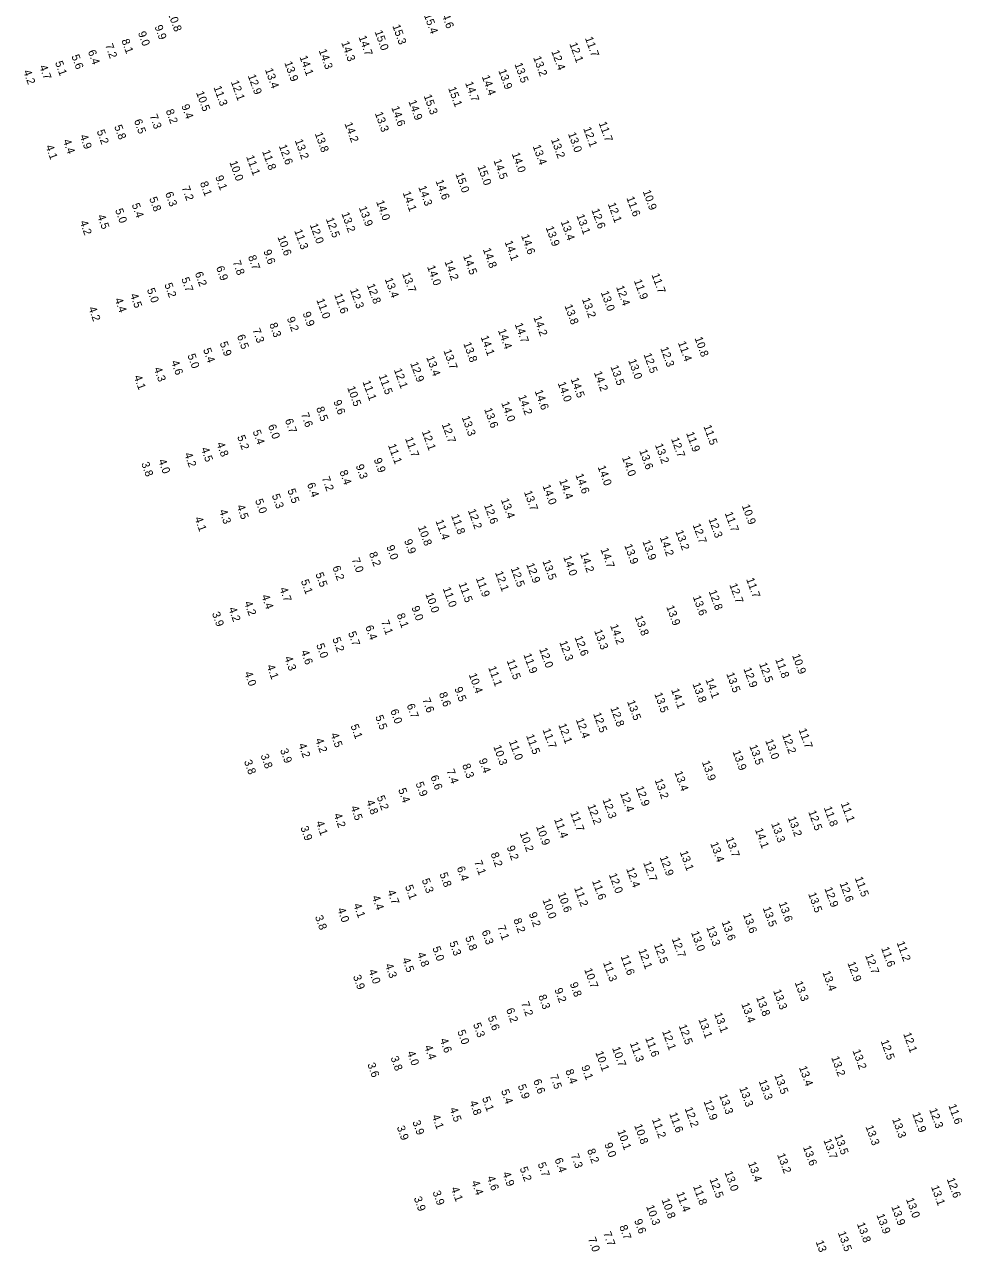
# Model space of a CAD drawing. Extents: x 815385 to 820851, y 582449 to 604245.
# Drawn here: x 819938 to 820525, y 591711 to 592474 of the extents above; entities that cross this region are included whole.
import ezdxf

# ---------------------------------------------------------------- set-up
doc = ezdxf.new("R2010")
doc.units = 0
doc.layers.add('V-TOPO-SOUN-112008', color=7, linetype='Continuous')

msp = doc.modelspace()

# ---------------------------------------------------------------- texts
at = {"layer": 'V-TOPO-SOUN-112008'}
for s, p in [('10.8 ', (820027.94, 592480.84)), ('15.4 ', (820187.99, 592479.46)), ('14.6 ', (820197.95, 592482.8)), ('9.0', (820009.34, 592468.38)), ('9.9', (820019.71, 592472.29)), ('15.0 ', (820157.19, 592469.11)), ('15.3 ', (820168.27, 592472.72)), ('7.2', (819988.81, 592460.69)), ('8.1', (819998.99, 592463.65)), ('14.3 ', (820136.35, 592462.24)), ('14.7 ', (820147.16, 592465.75)), ('12.1 ', (820278.88, 592461.51)), ('11.7 ', (820288.62, 592465.08)), ('5.6', (819967.77, 592453.87)), ('6.4', (819978.04, 592456.75)), ('14.1 ', (820110.29, 592453.26)), ('14.3 ', (820122.26, 592457.36)), ('12.4 ', (820267.59, 592456.73)), ('4.7', (819947.71, 592447.38)), ('5.1', (819957.5, 592449.83)), ('13.4 ', (820088.68, 592445.36)), ('13.9 ', (820100.78, 592449.69)), ('13.5 ', (820244.56, 592448.81)), ('13.2 ', (820256.27, 592452.93)), ('4.2', (819937.67, 592444.31)), ('12.1 ', (820067.37, 592437.78)), ('12.9 ', (820077.98, 592441.55)), ('14.4 ', (820224.16, 592441.02)), ('13.9 ', (820234.48, 592444.78)), ('10.5 ', (820045.64, 592431.04)), ('11.3 ', (820056.54, 592434.36)), ('15.1 ', (820203.13, 592433.8)), ('14.7 ', (820213.75, 592437.04)), ('9.4', (820036.43, 592422.8)), ('14.9 ', (820178.33, 592425.5)), ('15.3 ', (820187.85, 592429)), ('7.3', (820016.58, 592416.55)), ('8.2', (820026.71, 592419.74)), ('13.3 ', (820157.34, 592418.12)), ('14.6 ', (820167.62, 592421.69)), ('5.2', (819983.59, 592406.93)), ('5.8', (819994.49, 592409.92)), ('6.5', (820006.86, 592413.5)), ('14.2 ', (820138.39, 592411.62)), ('12.1 ', (820287.52, 592408.65)), ('11.7 ', (820297.2, 592411.99)), ('4.4', (819962.49, 592400.99)), ('4.9', (819972.99, 592403.95)), ('13.2 ', (820107.33, 592401.07)), ('13.8 ', (820119.81, 592405.42)), ('13.2 ', (820267.38, 592401.68)), ('13.0 ', (820278.01, 592405.38)), ('4.1', (819951.62, 592397.45)), ('11.8 ', (820086.9, 592394.32)), ('12.6 ', (820097.34, 592397.7)), ('14.0 ', (820242.89, 592392.77)), ('13.4 ', (820255.97, 592397.55)), ('10.0 ', (820066.45, 592387.54)), ('11.1 ', (820076.95, 592390.99)), ('15.0 ', (820221.42, 592384.83)), ('14.5 ', (820231.45, 592388.59)), ('9.1', (820057.63, 592378.31)), ('15.0 ', (820207.67, 592380.19)), ('7.2', (820036.7, 592371.72)), ('8.1', (820048.07, 592374.61)), ('14.3 ', (820184.5, 592371.96)), ('14.6 ', (820195.28, 592375.77)), ('10.9 ', (820324.72, 592369.32)), ('5.8', (820016.36, 592364.94)), ('6.3', (820026.3, 592368.09)), ('14.0 ', (820158.13, 592362.85)), ('14.1 ', (820174.71, 592368.45)), ('11.6 ', (820314.48, 592365.28)), ('5.0', (819995.04, 592357.68)), ('5.4', (820005.43, 592361.02)), ('13.2 ', (820136.44, 592355.45)), ('13.9 ', (820147.35, 592359.14)), ('13.1 ', (820283.28, 592354.19)), ('12.6 ', (820292.65, 592357.69)), ('12.1 ', (820302.9, 592361.44)), ('4.2', (819972.96, 592350.23)), ('4.5', (819983.93, 592353.94)), ('12.0 ', (820116.69, 592348.38)), ('12.5 ', (820126.75, 592352.06)), ('13.9 ', (820264.07, 592346.71)), ('13.4 ', (820273.46, 592350.36)), ('10.6 ', (820096.51, 592340.81)), ('11.3 ', (820106.98, 592344.76)), ('14.6 ', (820248.73, 592341.6)), ('9.6', (820087.7, 592331.98)), ('14.8 ', (820224.81, 592333.09)), ('14.1 ', (820238.44, 592337.67)), ('7.8', (820068.49, 592325.21)), ('8.7', (820078.1, 592328.51)), ('14.2 ', (820200.88, 592325.4)), ('14.5 ', (820212.48, 592328.93)), ('6.2', (820044.87, 592318.17)), ('6.9', (820058.13, 592321.75)), ('13.7 ', (820174.38, 592317.84)), ('14.0 ', (820189.99, 592322.19)), ('11.7 ', (820330.22, 592317.25)), ('5.0', (820014.91, 592307.94)), ('5.2', (820025.82, 592311.18)), ('5.7', (820036.39, 592314.68)), ('12.8 ', (820152.37, 592310.76)), ('13.4 ', (820163.53, 592314.47)), ('12.4 ', (820308.05, 592309.58)), ('11.9 ', (820319.2, 592313.5)), ('4.4', (819994.75, 592301.84)), ('4.5', (820004.41, 592304.65)), ('11.0 ', (820120.81, 592301.46)), ('11.6 ', (820131.96, 592304.67)), ('12.3 ', (820141.8, 592307.8)), ('13.2 ', (820286.72, 592301.93)), ('13.0 ', (820298.51, 592306.21)), ('4.2', (819978.39, 592296.39)), ('9.9', (820112.21, 592293.14)), ('13.8 ', (820275.82, 592297.82)), ('8.3', (820091.36, 592286.34)), ('9.2', (820102.35, 592289.98)), ('14.7 ', (820244.72, 592286.29)), ('14.2 ', (820256.4, 592290.62)), ('6.5', (820071.17, 592278.95)), ('7.3', (820080.81, 592282.82)), ('14.1 ', (820223.44, 592278.34)), ('14.4 ', (820234.26, 592282.47)), ('10.8 ', (820357.07, 592277.62)), ('5.4', (820050.02, 592270.47)), ('5.9', (820060.4, 592274.54)), ('13.8 ', (820212.59, 592274.25)), ('12.3 ', (820335.68, 592271.33)), ('11.4 ', (820346.69, 592274.79)), ('4.6', (820030.01, 592262.83)), ('5.0', (820040.25, 592266.89)), ('13.4 ', (820189.48, 592265.59)), ('13.7 ', (820200.19, 592269.76)), ('13.0 ', (820315.62, 592263.66)), ('12.5 ', (820325.21, 592267.41)), ('4.3', (820019.27, 592258.6)), ('12.1 ', (820169.24, 592257.88)), ('12.9 ', (820179.41, 592261.87)), ('14.2 ', (820294.21, 592256.06)), ('13.5 ', (820304.53, 592259.8)), ('4.1', (820006.77, 592253.58)), ('11.1 ', (820149.62, 592250.31)), ('11.5 ', (820159.7, 592254.11)), ('14.0 ', (820271.59, 592249.51)), ('14.5 ', (820279.67, 592252.05)), ('10.5 ', (820140.05, 592246.7)), ('14.2 ', (820246.9, 592241.25)), ('14.6 ', (820257.21, 592244.49)), ('8.5', (820120.66, 592233.87)), ('9.6', (820131.41, 592238.07)), ('13.6 ', (820225.63, 592233.16)), ('14.0 ', (820236.29, 592237.1)), ('6.7', (820101.13, 592226.39)), ('7.6', (820111.12, 592230.18)), ('13.3 ', (820211.62, 592228.14)), ('5.4', (820080.98, 592219.34)), ('6.0', (820090.57, 592222.82)), ('12.1 ', (820186.71, 592219.21)), ('12.7 ', (820199.14, 592223.78)), ('11.9 ', (820351.81, 592218.23)), ('11.5 ', (820362.64, 592222.54)), ('4.8', (820058.41, 592211.71)), ('5.2', (820071.31, 592216.04)), ('11.1 ', (820165.56, 592210.71)), ('11.7 ', (820176.21, 592214.89)), ('13.2 ', (820332.36, 592210.9)), ('12.7 ', (820342.42, 592214.68)), ('4.2', (820038.3, 592205.21)), ('4.5', (820048.69, 592208.52)), ('9.9', (820156.62, 592201.78)), ('14.0 ', (820311.72, 592203)), ('13.6 ', (820322.51, 592207.24)), ('3.8', (820011.39, 592199.33)), ('4.0', (820022.02, 592201.16)), ('8.4', (820135.24, 592194.2)), ('9.3', (820145.39, 592197.86)), ('14.0 ', (820296.54, 592197.16)), ('6.4', (820114.95, 592186.42)), ('7.2', (820124.19, 592190.27)), ('14.4 ', (820272.48, 592188.66)), ('14.6 ', (820282.65, 592192.11)), ('5.3', (820092.96, 592179.35)), ('5.5', (820102.7, 592182.61)), ('13.7 ', (820250.51, 592181.46)), ('14.0 ', (820262.12, 592185.25)), ('4.5', (820070.99, 592172.64)), ('5.0', (820082.49, 592176.25)), ('12.6 ', (820225.54, 592173.21)), ('13.4 ', (820236.09, 592176.66)), ('10.9 ', (820386.63, 592172.87)), ('4.1', (820044.71, 592165.07)), ('4.3', (820060.03, 592169.7)), ('11.4 ', (820195.26, 592163.35)), ('11.8 ', (820204.99, 592166.7)), ('12.2 ', (820215.47, 592169.98)), ('12.3 ', (820365.8, 592164.52)), ('11.7 ', (820375.96, 592168.22)), ('10.8 ', (820184.22, 592159.6)), ('13.2 ', (820345.1, 592156.83)), ('12.7 ', (820355.89, 592160.92)), ('9.9', (820175.63, 592151.06)), ('13.9 ', (820313.18, 592148.08)), ('13.9 ', (820324.48, 592150.56)), ('14.2 ', (820335.35, 592153.06)), ('8.2', (820153.67, 592143.17)), ('9.0', (820164.55, 592147.34)), ('14.0 ', (820275.06, 592140.77)), ('14.2 ', (820285.56, 592142.89)), ('14.7 ', (820298.34, 592145.63)), ('6.2', (820130.81, 592134.44)), ('7.0', (820142.84, 592139.42)), ('12.5 ', (820242.24, 592133.83)), ('12.9 ', (820251.94, 592136.27)), ('13.5 ', (820262.05, 592138.23)), ('5.1', (820111.11, 592125.89)), ('5.5', (820120.22, 592130.3)), ('11.9 ', (820220.44, 592127.58)), ('12.1 ', (820232.42, 592131.14)), ('11.7 ', (820389.34, 592127.01)), ('4.7', (820097.77, 592121.07)), ('10.0 ', (820188.88, 592117.71)), ('11.0 ', (820199.76, 592121.19)), ('11.5 ', (820209.65, 592124.18)), ('12.8 ', (820365.91, 592119.36)), ('12.7 ', (820378.82, 592123.56)), ('4.2', (820075.69, 592112.39)), ('4.4', (820086.49, 592116.52)), ('13.6 ', (820356, 592115.97)), ('3.9', (820055.55, 592105.66)), ('4.2', (820065.9, 592108.63)), ('8.1', (820171.01, 592104.79)), ('9.0', (820180.21, 592109.33)), ('13.8 ', (820319.75, 592103.39)), ('13.9 ', (820339.4, 592109.78)), ('6.4', (820151.34, 592097.27)), ('7.1', (820161.19, 592100.51)), ('13.3 ', (820294.36, 592094.73)), ('14.2 ', (820304.34, 592097.99)), ('5.2', (820130.8, 592089.76)), ('5.7', (820140.59, 592093.45)), ('12.3 ', (820272.56, 592087.64)), ('12.6 ', (820282.11, 592090.73)), ('4.6', (820111.09, 592081.84)), ('5.0', (820120.7, 592085.92)), ('11.9 ', (820250.17, 592079.8)), ('12.0 ', (820260.03, 592083.27)), ('10.9 ', (820418.01, 592079.41)), ('4.1', (820089.73, 592072.75)), ('4.3', (820100.79, 592078.01)), ('11.1 ', (820228.15, 592071.79)), ('11.5 ', (820239.74, 592076.02)), ('12.5 ', (820397.38, 592074.09)), ('11.8 ', (820407.48, 592076.9)), ('4.0', (820075.82, 592068.41)), ('10.4 ', (820216.01, 592067.39)), ('14.1 ', (820363.89, 592064.24)), ('13.5 ', (820376.93, 592067.88)), ('12.9 ', (820387.63, 592070.98)), ('9.5', (820207.03, 592058.75)), ('14.1 ', (820342.45, 592057.85)), ('13.8 ', (820355.8, 592061.54)), ('7.6', (820186.94, 592051.84)), ('8.6', (820197.37, 592055.52)), ('13.5 ', (820314.91, 592050.53)), ('13.5 ', (820331.96, 592055.3)), ('5.5', (820157.6, 592041.15)), ('6.0', (820167.01, 592044.88)), ('6.7', (820177.21, 592048.29)), ('12.5 ', (820293.73, 592042.87)), ('12.8 ', (820304.48, 592046.53)), ('5.1', (820142.14, 592035.45)), ('12.1 ', (820271.98, 592035.98)), ('12.4 ', (820282.9, 592039.29)), ('4.2', (820120.1, 592026.74)), ('4.5', (820129.63, 592030.09)), ('11.5 ', (820251.83, 592029.26)), ('11.7 ', (820262.09, 592032.91)), ('13.0 ', (820401.22, 592026.15)), ('12.2 ', (820411.77, 592029.63)), ('11.7 ', (820422.09, 592032.92)), ('3.9', (820098.13, 592020.29)), ('4.2', (820109.53, 592023.6)), ('10.3 ', (820231.33, 592022.44)), ('11.0 ', (820241.08, 592025.63)), ('13.9 ', (820380.82, 592019.24)), ('13.5 ', (820391.33, 592022.72)), ('3.8', (820075.59, 592013.21)), ('3.8', (820085.93, 592016.91)), ('8.3', (820211.89, 592010.84)), ('9.4', (820222.27, 592014.1)), ('13.9 ', (820361.65, 592012.76)), ('6.6', (820192.05, 592003.6)), ('7.4', (820202.11, 592007.43)), ('13.4 ', (820344.53, 592006.28)), ('5.4', (820171.91, 591995.53)), ('5.9', (820182.79, 591999.46)), ('12.9 ', (820320.3, 591996.88)), ('13.2 ', (820332.15, 592001.48)), ('5.2', (820158.52, 591990.93)), ('12.3 ', (820299.56, 591989.15)), ('12.4 ', (820310.52, 591993.26)), ('4.5', (820142.16, 591984.55)), ('4.8', (820151.93, 591988.18)), ('11.7 ', (820279.4, 591981.09)), ('12.2 ', (820290.15, 591985.47)), ('12.5 ', (820428.1, 591981.69)), ('11.8 ', (820437.84, 591984.21)), ('11.1 ', (820448.46, 591986.83)), ('4.1', (820120.47, 591975.08)), ('4.2', (820131.62, 591979.87)), ('11.4 ', (820269.32, 591976.92)), ('13.3 ', (820404.94, 591974.2)), ('13.2 ', (820415.4, 591977.86)), ('3.9', (820110.81, 591971.85)), ('10.2 ', (820247.83, 591968.39)), ('10.9 ', (820258.04, 591972.46)), ('14.1 ', (820394.83, 591970.57)), ('9.2', (820239.7, 591959.63)), ('13.4 ', (820366.87, 591961.91)), ('13.7 ', (820376.52, 591964.92)), ('7.1', (820219.35, 591950.41)), ('8.2', (820229.66, 591955.42)), ('12.7 ', (820324.98, 591949.82)), ('12.9 ', (820335.34, 591953.28)), ('13.1 ', (820347.88, 591956.49)), ('5.8', (820197.75, 591942.83)), ('6.4', (820208.51, 591946.68)), ('12.0 ', (820303.56, 591942.42)), ('12.4 ', (820314.36, 591946.03)), ('5.1', (820176.18, 591935.06)), ('5.3', (820186.62, 591939.09)), ('11.6 ', (820293.05, 591938.36)), ('12.6 ', (820447.68, 591936.98)), ('11.5 ', (820457.19, 591940.28)), ('4.4', (820155.48, 591928.5)), ('4.7', (820165.09, 591931.95)), ('10.6 ', (820271.57, 591930.49)), ('11.2 ', (820281.83, 591934.11)), ('13.5 ', (820428.07, 591930.42)), ('12.9 ', (820438.21, 591933.72)), ('4.0', (820133.86, 591920.82)), ('4.1', (820143.92, 591923.59)), ('10.0 ', (820262.05, 591926.59)), ('13.5 ', (820399.68, 591921.53)), ('13.6 ', (820409.61, 591924.6)), ('3.8', (820119.92, 591916.09)), ('8.2', (820243.9, 591914.24)), ('9.2', (820253.48, 591918)), ('13.6 ', (820374, 591912.82)), ('13.6 ', (820387.34, 591917.48)), ('6.3', (820224.04, 591906.88)), ('7.1', (820233.89, 591909.79)), ('13.0 ', (820354.87, 591906.24)), ('13.3 ', (820364.47, 591909.47)), ('5.0', (820193.26, 591896.62)), ('5.3', (820203.83, 591899.93)), ('5.8', (820213.77, 591903.17)), ('12.5 ', (820331.71, 591898.54)), ('12.7 ', (820342.85, 591902.26)), ('11.6 ', (820473.65, 591896.45)), ('11.2 ', (820483.34, 591899.92)), ('4.5', (820174.37, 591889.63)), ('4.8', (820183.79, 591893.02)), ('11.6 ', (820310.9, 591891.29)), ('12.1 ', (820321.94, 591895.19)), ('12.7 ', (820463.64, 591891.98)), ('4.0', (820153.38, 591882.37)), ('4.3', (820163.68, 591885.97)), ('10.7 ', (820288.14, 591883.1)), ('11.3 ', (820299.89, 591887.34)), ('13.4 ', (820436.95, 591881.39)), ('12.9 ', (820452.61, 591887.18)), ('3.9', (820143.66, 591878.83)), ('9.8', (820279.1, 591874.25)), ('13.3 ', (820419.65, 591874.97)), ('8.3', (820259.42, 591866.51)), ('9.2', (820269.55, 591870.62)), ('13.3 ', (820406.2, 591869.81)), ('7.2', (820248.71, 591862.17)), ('13.4 ', (820386.29, 591861.57)), ('13.8 ', (820395.55, 591865.66)), ('5.6', (820227.84, 591853.25)), ('6.2', (820239.32, 591858.13)), ('13.1 ', (820359.48, 591851.91)), ('13.1 ', (820369.34, 591855.35)), ('5.0', (820208.84, 591844.5)), ('5.3', (820218.67, 591848.92)), ('12.1 ', (820336.82, 591844.45)), ('12.5 ', (820347.18, 591847.93)), ('4.6', (820197.97, 591839.28)), ('11.3 ', (820316.67, 591837.07)), ('11.6 ', (820326.25, 591840.24)), ('12.5 ', (820473.34, 591838.36)), ('12.1 ', (820487.45, 591842.91)), ('3.8', (820167.14, 591828.04)), ('4.0', (820177.46, 591831.34)), ('4.4', (820188.22, 591835.01)), ('10.1 ', (820295.09, 591831.27)), ('10.7 ', (820305.56, 591834.04)), ('13.2 ', (820442.48, 591828.1)), ('13.2 ', (820455.78, 591832.38)), ('3.6', (820152.64, 591823.96)), ('8.4', (820276.37, 591819.9)), ('9.1', (820286.29, 591822.39)), ('13.4 ', (820422.32, 591821.95)), ('6.6', (820256.28, 591813.67)), ('7.5', (820266.71, 591816.64)), ('13.3 ', (820397.15, 591813.3)), ('13.5 ', (820406.92, 591816.97)), ('5.4', (820236.16, 591807.33)), ('5.9', (820246.64, 591810.48)), ('13.3 ', (820385.01, 591809.02)), ('4.8', (820216.45, 591800.3)), ('5.1', (820224.31, 591802.76)), ('12.9 ', (820362.69, 591800.68)), ('13.3 ', (820372.48, 591804.37)), ('11.6 ', (820515.64, 591798.16)), ('4.1', (820192.96, 591791.57)), ('4.5', (820203.98, 591796.11)), ('11.6 ', (820341.27, 591792.93)), ('12.2 ', (820350.88, 591796.3)), ('12.9 ', (820493.11, 591793.06)), ('12.3 ', (820503.68, 591795.6)), ('3.9', (820171.03, 591784.66)), ('3.9', (820180.78, 591787.97)), ('10.1 ', (820308.79, 591782.17)), ('10.8 ', (820319.36, 591785.7)), ('11.2 ', (820330.47, 591789.44)), ('13.3 ', (820463.87, 591784.95)), ('13.3 ', (820480.53, 591789.54)), ('13.7 ', (820437.6, 591776.46)), ('13.5 ', (820444.49, 591779.16)), ('7.3', (820279.77, 591767.13)), ('8.2', (820289.94, 591770.26)), ('9.0', (820300.7, 591774.01)), ('13.2 ', (820408.68, 591767.43)), ('13.6 ', (820424.83, 591772.2)), ('5.2', (820247.8, 591758.94)), ('5.7', (820259.06, 591761.73)), ('6.4', (820269.62, 591764.49)), ('13.4 ', (820390.44, 591762.18)), ('4.6', (820227.33, 591753.24)), ('4.9', (820237.07, 591755.85)), ('12.5 ', (820366.44, 591752.07)), ('13.0 ', (820375.81, 591756.32)), ('12.6 ', (820514.67, 591752.12)), ('3.9', (820193.39, 591744.06)), ('4.1', (820204.88, 591746.42)), ('4.4', (820217.62, 591750.39)), ('11.8 ', (820356.14, 591747.66)), ('13.1 ', (820504.82, 591747.38)), ('3.9', (820181.66, 591740.35)), ('10.8 ', (820336.47, 591739.21)), ('11.4 ', (820345.65, 591743.38)), ('13.0 ', (820489.16, 591739.61)), ('10.3 ', (820326.83, 591735.09)), ('13.9 ', (820470.75, 591729.69)), ('13.9 ', (820480, 591734.92)), ('8.7', (820310.04, 591722.54)), ('9.6', (820319.35, 591726.29)), ('13.8 ', (820458.52, 591724.2)), ('7.0', (820290.48, 591714.95)), ('7.7', (820300, 591718.48)), ('13.5 ', (820446.61, 591718.68)), ('13.7 ', (820432.74, 591713.02))]:
    msp.add_text(s, height=5, rotation=289.902, dxfattribs=at).set_placement(p)

doc.saveas('drawing.dxf')
